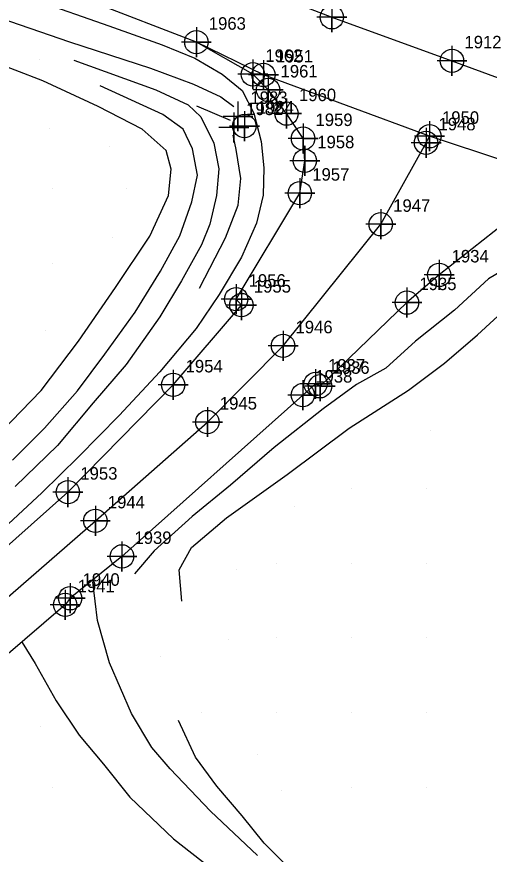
# Model space of a CAD drawing. Extents: x 1497074 to 1501343, y 481943 to 486114.
# Drawn here: x 1499843.4 to 1499938.2, y 482583.9 to 482751.7 of the extents above; entities that cross this region are included whole.
import ezdxf

# ---------------------------------------------------------------- set-up
doc = ezdxf.new("R2010")
doc.units = 0
for name, color, linetype in [('Exist DTM Breakline', 7, 'Continuous'), ('Exist DTM Breakline Cogo Number', 7, 'Continuous'), ('Exist DTM Breakline Cogo Point CELL', 7, 'Continuous'), ('Exist DTM Crownline', 7, 'Continuous'), ('Exist DTM Crownline Cogo Number', 7, 'Continuous'), ('Exist DTM Crownline Cogo Point CELL', 7, 'Continuous'), ('Exist DTM Regular Point CELL', 7, 'Continuous'), ('Exist DTM Spot Elevation CELL', 7, 'Continuous'), ('Exist DTM Spot Elevation Cogo Number', 7, 'Continuous'), ('Exist Roads EOP', 7, 'Continuous'), ('Exist Roads EOP Cogo Number', 7, 'Continuous'), ('Exist Roads EOP Cogo Point CELL', 7, 'Continuous'), ('Exist Structure Minor Pipes CMP 15 Inch Cogo Number', 7, 'Continuous'), ('PH Exist DTM Breakline', 7, 'Continuous'), ('PH Exist DTM Point', 7, 'Continuous')]:
    doc.layers.add(name, color=color, linetype=linetype)

msp = doc.modelspace()

# ---------------------------------------------------------------- linework, layer by layer
at = {"layer": 'Exist DTM Breakline'}
msp.add_lwpolyline([(1499975.28, 482711.55), (1499956.18, 482717.8), (1499926.19, 482727.72), (1499892.88, 482740), (1499879.42, 482746.57)], dxfattribs=at)
at = {"layer": 'Exist DTM Breakline Cogo Point CELL'}
for points in [[(1499892.88, 482743), (1499892.88, 482737), (1499892.88, 482740), (1499895.88, 482740), (1499889.88, 482740)], [(1499926.19, 482730.72), (1499926.19, 482724.72), (1499926.19, 482727.72), (1499929.19, 482727.72), (1499923.19, 482727.72)]]:
    msp.add_lwpolyline(points, dxfattribs=at)
for centre in [(1499892.88, 482740), (1499926.19, 482727.72)]:
    msp.add_circle(centre, 2.34, dxfattribs=at)
at = {"layer": 'Exist DTM Crownline'}
for points in [[(1499395.36, 482985.02), (1499443.87, 482960.81), (1499493.08, 482936.36), (1499540.5, 482912.88), (1499586.46, 482890.36), (1499633.9, 482867.41), (1499680.88, 482845.25), (1499726.12, 482824.18), (1499773.19, 482803.77), (1499819.04, 482785.34), (1499906.6, 482751.56), (1499930.69, 482742.84), (1499979.87, 482724.77), (1500026.26, 482708.17), (1500077.15, 482689.67), (1500127.52, 482671.55), (1500177.68, 482653.78), (1500231.5, 482634.52), (1500279.65, 482617.19), (1500328.73, 482599.71), (1500369.66, 482584.94)], [(1499827.14, 482622.78), (1499859.17, 482650.66), (1499881.64, 482670.46), (1499896.81, 482685.73), (1499916.4, 482710.08), (1499925.49, 482726.41), (1499926.19, 482727.72)]]:
    msp.add_lwpolyline(points, dxfattribs=at)
at = {"layer": 'Exist DTM Crownline Cogo Point CELL'}
for points in [[(1499906.6, 482754.56), (1499906.6, 482748.56), (1499906.6, 482751.56), (1499909.6, 482751.56), (1499903.6, 482751.56)], [(1499930.69, 482745.84), (1499930.69, 482739.84), (1499930.69, 482742.84), (1499933.69, 482742.84), (1499927.69, 482742.84)], [(1499925.49, 482729.41), (1499925.49, 482723.41), (1499925.49, 482726.41), (1499928.49, 482726.41), (1499922.49, 482726.41)], [(1499916.4, 482713.08), (1499916.4, 482707.08), (1499916.4, 482710.08), (1499919.4, 482710.08), (1499913.4, 482710.08)], [(1499896.81, 482688.73), (1499896.81, 482682.73), (1499896.81, 482685.73), (1499899.81, 482685.73), (1499893.81, 482685.73)], [(1499881.64, 482673.46), (1499881.64, 482667.46), (1499881.64, 482670.46), (1499884.64, 482670.46), (1499878.64, 482670.46)], [(1499859.17, 482653.66), (1499859.17, 482647.66), (1499859.17, 482650.66), (1499862.17, 482650.66), (1499856.17, 482650.66)]]:
    msp.add_lwpolyline(points, dxfattribs=at)
for centre in [(1499906.6, 482751.56), (1499930.69, 482742.84), (1499925.49, 482726.41), (1499916.4, 482710.08), (1499896.81, 482685.73), (1499881.64, 482670.46), (1499859.17, 482650.66)]:
    msp.add_circle(centre, 2.34, dxfattribs=at)
at = {"layer": 'Exist DTM Regular Point CELL'}
msp.add_lwpolyline([(1499889.06, 482732.76), (1499889.06, 482726.76), (1499889.06, 482729.76), (1499892.06, 482729.76), (1499886.06, 482729.76)], dxfattribs=at)
msp.add_circle((1499889.06, 482729.76), 2.34, dxfattribs=at)
at = {"layer": 'Exist DTM Spot Elevation CELL'}
for points in [[(1499887.77, 482734.71), (1499887.77, 482728.71), (1499887.77, 482731.71), (1499890.77, 482731.71), (1499884.77, 482731.71)], [(1499886.92, 482732.46), (1499886.92, 482726.46), (1499886.92, 482729.46), (1499889.92, 482729.46), (1499883.92, 482729.46)]]:
    msp.add_lwpolyline(points, dxfattribs=at)
at = {"layer": 'Exist Roads EOP'}
for points in [[(1499821.72, 482628.04), (1499853.66, 482656.41), (1499874.77, 482677.9), (1499888.46, 482693.89), (1499887.41, 482695.08), (1499900.17, 482716.32), (1499901.17, 482722.81), (1499900.82, 482727.27), (1499897.51, 482732.26), (1499893.81, 482737), (1499890.76, 482740.13), (1499879.42, 482746.57), (1499858.29, 482754.73), (1499814.16, 482772.08), (1499767.71, 482791.06), (1499743.71, 482801.5), (1499721.28, 482811.45), (1499698.51, 482821.61), (1499675.14, 482832.32)], [(1500364.14, 482572.31), (1500324.1, 482586.71), (1500274.47, 482604.24), (1500226.4, 482621.51), (1500172.89, 482640.65), (1500123.05, 482658.39), (1500072.51, 482676.64), (1500021.62, 482694.94), (1499975.28, 482711.55), (1499955.26, 482716.33), (1499949.38, 482714.38), (1499941.38, 482710.37), (1499928.12, 482699.94), (1499921.66, 482694.39), (1499904.23, 482677.62), (1499903.33, 482678.08), (1499900.77, 482675.86), (1499864.51, 482643.53), (1499854.11, 482635.15), (1499853.12, 482633.84), (1499832.56, 482616.27)]]:
    msp.add_lwpolyline(points, dxfattribs=at)
at = {"layer": 'Exist Roads EOP Cogo Point CELL'}
for points in [[(1499879.42, 482749.57), (1499879.42, 482743.57), (1499879.42, 482746.57), (1499882.42, 482746.57), (1499876.42, 482746.57)], [(1499890.76, 482743.13), (1499890.76, 482737.13), (1499890.76, 482740.13), (1499893.76, 482740.13), (1499887.76, 482740.13)], [(1499893.81, 482740), (1499893.81, 482734), (1499893.81, 482737), (1499896.81, 482737), (1499890.81, 482737)], [(1499897.51, 482735.26), (1499897.51, 482729.26), (1499897.51, 482732.26), (1499900.51, 482732.26), (1499894.51, 482732.26)], [(1499900.82, 482730.27), (1499900.82, 482724.27), (1499900.82, 482727.27), (1499903.82, 482727.27), (1499897.82, 482727.27)], [(1499901.17, 482725.81), (1499901.17, 482719.81), (1499901.17, 482722.81), (1499904.17, 482722.81), (1499898.17, 482722.81)], [(1499900.17, 482719.32), (1499900.17, 482713.32), (1499900.17, 482716.32), (1499903.17, 482716.32), (1499897.17, 482716.32)], [(1499928.12, 482702.94), (1499928.12, 482696.94), (1499928.12, 482699.94), (1499931.12, 482699.94), (1499925.12, 482699.94)], [(1499887.41, 482698.08), (1499887.41, 482692.08), (1499887.41, 482695.08), (1499890.41, 482695.08), (1499884.41, 482695.08)], [(1499921.66, 482697.39), (1499921.66, 482691.39), (1499921.66, 482694.39), (1499924.66, 482694.39), (1499918.66, 482694.39)], [(1499888.46, 482696.89), (1499888.46, 482690.89), (1499888.46, 482693.89), (1499891.46, 482693.89), (1499885.46, 482693.89)], [(1499874.77, 482680.9), (1499874.77, 482674.9), (1499874.77, 482677.9), (1499877.77, 482677.9), (1499871.77, 482677.9)], [(1499903.33, 482681.08), (1499903.33, 482675.08), (1499903.33, 482678.08), (1499906.33, 482678.08), (1499900.33, 482678.08)], [(1499904.23, 482680.62), (1499904.23, 482674.62), (1499904.23, 482677.62), (1499907.23, 482677.62), (1499901.23, 482677.62)], [(1499900.77, 482678.86), (1499900.77, 482672.86), (1499900.77, 482675.86), (1499903.77, 482675.86), (1499897.77, 482675.86)], [(1499853.66, 482659.41), (1499853.66, 482653.41), (1499853.66, 482656.41), (1499856.66, 482656.41), (1499850.66, 482656.41)], [(1499864.51, 482646.53), (1499864.51, 482640.53), (1499864.51, 482643.53), (1499867.51, 482643.53), (1499861.51, 482643.53)], [(1499853.12, 482636.84), (1499853.12, 482630.84), (1499853.12, 482633.84), (1499856.12, 482633.84), (1499850.12, 482633.84)], [(1499854.11, 482638.15), (1499854.11, 482632.15), (1499854.11, 482635.15), (1499857.11, 482635.15), (1499851.11, 482635.15)]]:
    msp.add_lwpolyline(points, dxfattribs=at)
for centre in [(1499879.42, 482746.57), (1499890.76, 482740.13), (1499893.81, 482737), (1499897.51, 482732.26), (1499900.82, 482727.27), (1499901.17, 482722.81), (1499900.17, 482716.32), (1499928.12, 482699.94), (1499887.41, 482695.08), (1499888.46, 482693.89), (1499921.66, 482694.39), (1499903.33, 482678.08), (1499874.77, 482677.9), (1499904.23, 482677.62), (1499900.77, 482675.86), (1499853.66, 482656.41), (1499864.51, 482643.53), (1499854.11, 482635.15), (1499853.12, 482633.84)]:
    msp.add_circle(centre, 2.34, dxfattribs=at)
at = {"layer": 'PH Exist DTM Breakline'}
for points in [[(1499699.65, 482810.33), (1499725.57, 482798.37), (1499747.32, 482788.27), (1499771.85, 482778.33), (1499801.92, 482765.83), (1499832, 482754.22), (1499854, 482746.66), (1499870.21, 482741.39), (1499878.83, 482738.17)], [(1499846.96, 482755.15), (1499861.89, 482749.82), (1499872.54, 482746.02), (1499879.14, 482743.37), (1499884.63, 482740.14), (1499888.63, 482736.86), (1499890.94, 482732.38), (1499892.43, 482726.65), (1499892.96, 482721.36), (1499892.82, 482715.92), (1499891.49, 482710.3), (1499888.47, 482703.46), (1499884.01, 482696.03), (1499879.37, 482689.22), (1499872.08, 482680.5), (1499863.91, 482671.78), (1499855.8, 482663.48), (1499848.43, 482656.26), (1499838.84, 482647.39)], [(1499840.37, 482668.57), (1499848.3, 482676.77), (1499855.77, 482686.63), (1499863.23, 482697.43), (1499870.07, 482707.69), (1499873.83, 482715.83), (1499874.35, 482721.11), (1499873.37, 482724.88), (1499868.54, 482729.16), (1499859.73, 482733.68), (1499848.66, 482738.84), (1499837.47, 482743.12)], [(1499854.88, 482743), (1499871.27, 482736.99), (1499877.78, 482734), (1499880.33, 482731.6), (1499882.93, 482726.34), (1499883.91, 482721.21), (1499883.48, 482715.82), (1499882.11, 482710.13), (1499880.45, 482705.98), (1499876.47, 482698.77), (1499872.09, 482691.52), (1499865.34, 482681.98), (1499858.75, 482674.29), (1499851.56, 482665.75), (1499843.06, 482657.55)], [(1499842.52, 482662.8), (1499848.98, 482669.22), (1499855.61, 482676.73), (1499861.09, 482684.06), (1499867.15, 482692.45), (1499872.23, 482700.72), (1499876.09, 482707.8), (1499878.51, 482714.56), (1499879.62, 482719.93), (1499878.63, 482725.22), (1499876.81, 482729.11), (1499872.72, 482732.08), (1499860.15, 482737.81)], [(1499878.83, 482738.17), (1499884.31, 482735.59), (1499886.93, 482733.7)], [(1499879.45, 482733.81), (1499886.2, 482730.96)], [(1499880.07, 482697.27), (1499885.25, 482707.35), (1499887.78, 482713.93), (1499888.35, 482719.26), (1499887.4, 482725.07), (1499886.83, 482727.93)], [(1499955.48, 482705.41), (1499947.76, 482703.74), (1499942.92, 482702.04), (1499938.04, 482699.12), (1499931.2, 482692.86), (1499923.36, 482686.69), (1499917.39, 482681.28), (1499911.54, 482677.96), (1499904.87, 482673.08), (1499895, 482665.37), (1499886.3, 482657.82), (1499878.55, 482651.55), (1499870.97, 482644.65), (1499866.99, 482640.02)], [(1499876.52, 482634.54), (1499875.96, 482640.81), (1499878.42, 482645.32), (1499885.46, 482651.27), (1499897.65, 482659.96), (1499910.09, 482669.26), (1499921.97, 482676.84), (1499929.21, 482682.28), (1499935.82, 482687.91), (1499942.39, 482693.91), (1499947.38, 482696.79), (1499952.93, 482697.21), (1499962.43, 482695.02), (1499971.27, 482691.96), (1499987.6, 482684.42), (1500000.64, 482677.62), (1500015.27, 482671.74), (1500026.57, 482666.68), (1500033.41, 482663.12)], [(1499891.68, 482583.57), (1499882.25, 482592.51), (1499874.19, 482600.95), (1499870.52, 482605.23), (1499866.45, 482612.07), (1499862, 482622.21), (1499859.62, 482630.72), (1499858.66, 482638.42)], [(1499844.48, 482626.28), (1499847.08, 482622.08), (1499851.29, 482614.59), (1499855.9, 482607.7), (1499860.77, 482601.89), (1499866.1, 482595.29), (1499874.85, 482586.96), (1499885.89, 482578.3)], [(1499954.06, 482527.25), (1499948.49, 482530.61), (1499943.28, 482535.84), (1499936.03, 482543.98), (1499929.21, 482550.16), (1499923.39, 482555.61), (1499917.8, 482562.9), (1499911.99, 482568.79), (1499904.7, 482575.3), (1499898.15, 482580.91), (1499893.04, 482586.04), (1499888.61, 482591.55), (1499883.55, 482597.5), (1499879.24, 482603.3), (1499875.81, 482610.63)]]:
    msp.add_lwpolyline(points, dxfattribs=at)
at = {"layer": 'PH Exist DTM Point'}
for p, q in [((1499847.94, 482743.02), (1499847.94, 482743.02)), ((1499849.89, 482729.22), (1499849.89, 482729.22)), ((1499861.99, 482725.75), (1499861.99, 482725.75)), ((1499850.5, 482717.19), (1499850.5, 482717.19)), ((1499865.5, 482717.19), (1499865.5, 482717.19)), ((1499862.67, 482707.38), (1499862.67, 482707.38)), ((1499850.5, 482702.19), (1499850.5, 482702.19)), ((1499849.24, 482688.74), (1499849.24, 482688.74)), ((1499926.33, 482668.86), (1499926.33, 482668.86)), ((1499910.5, 482657.19), (1499910.5, 482657.19)), ((1499925.5, 482657.19), (1499925.5, 482657.19)), ((1499899.08, 482653.49), (1499899.08, 482653.49)), ((1499895.5, 482642.19), (1499895.5, 482642.19)), ((1499910.5, 482642.19), (1499910.5, 482642.19)), ((1499925.5, 482642.19), (1499925.5, 482642.19)), ((1499887.52, 482640.89), (1499887.52, 482640.89)), ((1499885.79, 482626.88), (1499885.79, 482626.88)), ((1499895.5, 482627.19), (1499895.5, 482627.19)), ((1499910.5, 482627.19), (1499910.5, 482627.19)), ((1499925.5, 482627.19), (1499925.5, 482627.19)), ((1499872.31, 482623.48), (1499872.31, 482623.48)), ((1499880.5, 482612.19), (1499880.5, 482612.19)), ((1499895.5, 482612.19), (1499895.5, 482612.19)), ((1499910.5, 482612.19), (1499910.5, 482612.19)), ((1499925.5, 482612.19), (1499925.5, 482612.19)), ((1499848.25, 482609.53), (1499848.25, 482609.53)), ((1499891.62, 482603.81), (1499891.62, 482603.81)), ((1499850.5, 482597.19), (1499850.5, 482597.19)), ((1499896.5, 482596.64), (1499896.5, 482596.64)), ((1499910.5, 482597.19), (1499910.5, 482597.19)), ((1499925.5, 482597.19), (1499925.5, 482597.19))]:
    msp.add_line(p, q, dxfattribs=at)

# ---------------------------------------------------------------- texts
at = {"layer": 'Exist DTM Breakline Cogo Number'}
for s, p in [('1951', (1499895.38, 482742.5)), ('1950', (1499928.69, 482730.22))]:
    msp.add_text(s, height=2.5, dxfattribs=at).set_placement(p)
at = {"layer": 'Exist DTM Crownline Cogo Number'}
for s, p in [('1912', (1499933.19, 482745.34)), ('1948', (1499927.99, 482728.91)), ('1947', (1499918.9, 482712.58)), ('1946', (1499899.31, 482688.24)), ('1945', (1499884.14, 482672.96)), ('1944', (1499861.67, 482653.16))]:
    msp.add_text(s, height=2.5, dxfattribs=at).set_placement(p)
at = {"layer": 'Exist DTM Spot Elevation Cogo Number'}
for s, p in [('1983', (1499890.27, 482734.21)), ('1982', (1499889.42, 482731.96))]:
    msp.add_text(s, height=2.5, dxfattribs=at).set_placement(p)
at = {"layer": 'Exist Roads EOP Cogo Number'}
for s, p in [('1963', (1499881.92, 482749.07)), ('1962', (1499893.26, 482742.63)), ('1961', (1499896.31, 482739.5)), ('1960', (1499900.01, 482734.76)), ('1959', (1499903.32, 482729.77)), ('1958', (1499903.67, 482725.32)), ('1957', (1499902.67, 482718.82)), ('1934', (1499930.62, 482702.44)), ('1956', (1499889.91, 482697.58)), ('1955', (1499890.96, 482696.39)), ('1935', (1499924.16, 482696.89)), ('1954', (1499877.27, 482680.4)), ('1937', (1499905.83, 482680.58)), ('1936', (1499906.73, 482680.12)), ('1938', (1499903.27, 482678.36)), ('1953', (1499856.16, 482658.91)), ('1939', (1499867.01, 482646.03)), ('1940', (1499856.61, 482637.65)), ('1941', (1499855.62, 482636.34))]:
    msp.add_text(s, height=2.5, dxfattribs=at).set_placement(p)
at = {"layer": 'Exist Structure Minor Pipes CMP 15 Inch Cogo Number'}
msp.add_text('1984', height=2.5, dxfattribs=at).set_placement((1499891.56, 482732.26))

doc.saveas('drawing.dxf')
